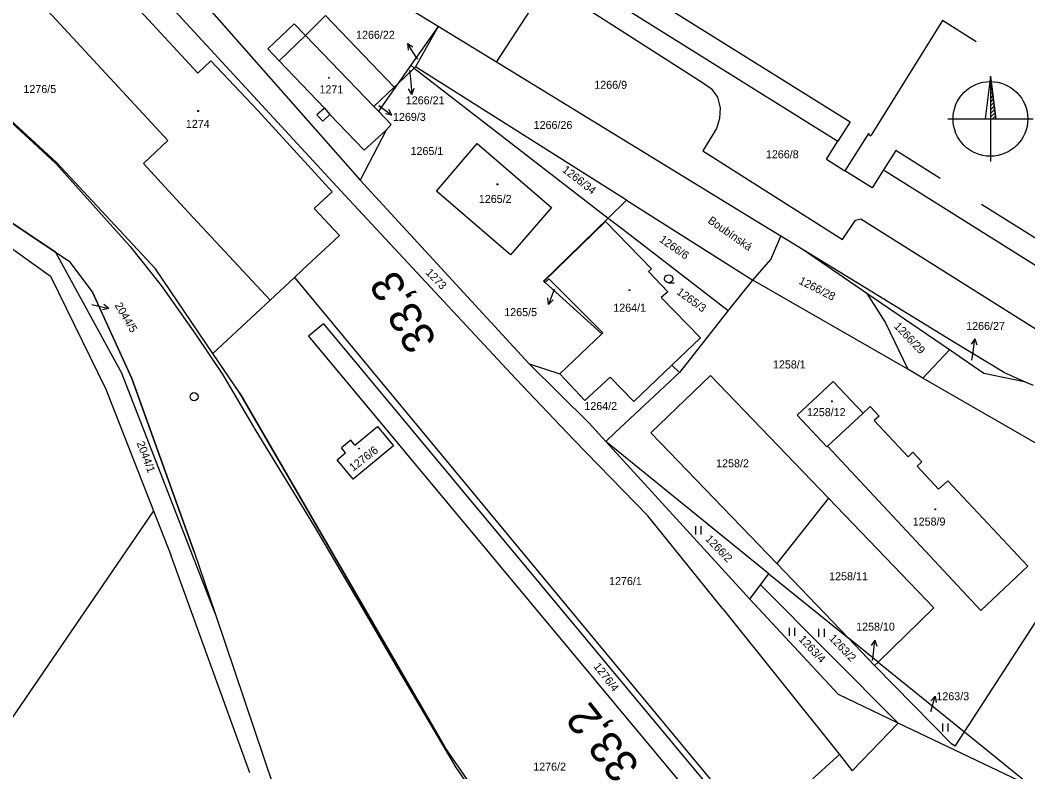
# Model space of a CAD drawing. Extents: x -805011 to -803920, y -1150790 to -1150234.
# Drawn here: x -804203.4 to -804014.7, y -1150647.5 to -1150506.7 of the extents above; entities that cross this region are included whole.
import ezdxf

# ---------------------------------------------------------------- set-up
doc = ezdxf.new("R2010")
doc.units = 0
for name, color, linetype in [('Default', 7, 'Continuous'), ('formát', 7, 'Continuous'), ('kilometráž - vrstava 7', 7, 'Continuous'), ('kn_celek - Cisla parcel pomocna', 7, 'Continuous'), ('kn_celek - Cisla pozemkovych parcel', 7, 'Continuous'), ('kn_celek - Cisla stavebnich parcel', 7, 'Continuous'), ('kn_celek - Dalsi prvky mapy popis', 7, 'Continuous'), ('kn_celek - Hranice parcel', 7, 'Continuous'), ('kn_celek - Vnitrni kresby', 7, 'Continuous'), ('kn_celek - Znacky budov', 7, 'Continuous'), ('kn_celek - Znacky kultur', 7, 'Continuous'), ('plochy - SZDC', 7, 'Continuous'), ('PSR_C2_2_trasa_Vimperk - Kabelová trasa', 7, 'Continuous')]:
    doc.layers.add(name, color=color, linetype=linetype)

# ---------------------------------------------------------------- blocks, each defined once
blk = doc.blocks.new('306')
at = {"layer": 'Default'}
for p, q in [((-5.2, 0), (-5.2, 15)), ((4.8, 0), (4.8, 15))]:
    blk.add_line(p, q, dxfattribs=at)
blk = doc.blocks.new('304')
at = {"layer": 'Default'}
blk.add_line((-0.1, 0), (9.9, 0), dxfattribs=at)
blk.add_circle((-0.1, 7.5), 7.5, dxfattribs=at)
blk = doc.blocks.new('402')
at = {"layer": 'Default'}
for p, q in [((-0.8, 0.8), (0.7, 0.8)), ((-0.8, 0.8), (-0.8, -0.7)), ((0.7, 0.8), (0.7, -0.7)), ((0.7, -0.7), (-0.8, -0.7))]:
    blk.add_line(p, q, dxfattribs=at)
blk = doc.blocks.new('Z61')
at = {"layer": 'Default'}
for p, q in [((0, 0), (30, 0)), ((30, 0), (19.2, 5.3)), ((30, 0), (19.2, -5.3))]:
    blk.add_line(p, q, dxfattribs=at)

msp = doc.modelspace()

# ---------------------------------------------------------------- linework, layer by layer
at = {"layer": 'formát'}
for p, q in [((-804021.69, -1150517.19), (-804021.69, -1150533.19)), ((-804021.69, -1150517.82), (-804021.62, -1150517.75)), ((-804021.69, -1150518.53), (-804021.54, -1150518.38)), ((-804021.69, -1150519.24), (-804021.46, -1150519.01)), ((-804021.69, -1150519.94), (-804021.38, -1150519.64)), ((-804021.69, -1150520.65), (-804021.31, -1150520.27)), ((-804021.69, -1150521.36), (-804021.23, -1150520.9)), ((-804021.69, -1150522.07), (-804021.15, -1150521.52)), ((-804021.69, -1150522.77), (-804021.07, -1150522.15)), ((-804021.69, -1150523.48), (-804020.99, -1150522.78)), ((-804021.69, -1150524.19), (-804020.91, -1150523.41)), ((-804029.69, -1150525.19), (-804013.69, -1150525.19)), ((-804021.69, -1150524.89), (-804020.83, -1150524.04)), ((-804021.28, -1150525.19), (-804020.76, -1150524.67))]:
    msp.add_line(p, q, dxfattribs=at)
for points in [[(-804021.69, -1150517.19), (-804022.69, -1150525.19)], [(-804021.69, -1150517.19), (-804020.69, -1150525.19)], [(-804021.69, -1150517.19), (-804021.69, -1150525.19), (-804020.69, -1150525.19), (-804021.69, -1150517.19)]]:
    msp.add_lwpolyline(points, dxfattribs=at)
msp.add_circle((-804021.69, -1150525.19), 7, dxfattribs=at)
at = {"layer": 'kilometráž - vrstava 7'}
msp.add_circle((-804170.87, -1150577.21), 0.75, dxfattribs=at)
at = {"layer": 'kn_celek - Cisla parcel pomocna'}
for p, q in [((-804128.97, -1150514.03), (-804129.25, -1150513.61)), ((-804130.49, -1150516.15), (-804130.35, -1150517.61)), ((-804190.03, -1150559.97), (-804189.75, -1150560.03)), ((-804025.16, -1150570.39), (-804025.01, -1150569.34)), ((-804043.76, -1150626.64), (-804043.67, -1150625.78))]:
    msp.add_line(p, q, dxfattribs=at)
at = {"layer": 'kn_celek - Hranice parcel'}
for p, q in [((-804111.38, -1150491.09), (-804050.27, -1150529.35)), ((-804192.55, -1150492.4), (-804170.14, -1150516.6)), ((-804099.45, -1150493.57), (-804047.98, -1150525.74)), ((-804206.45, -1150496.09), (-804175.77, -1150529.26)), ((-804181.12, -1150497.76), (-804142.6, -1150539.45)), ((-804169.49, -1150502.94), (-804139.75, -1150536.68)), ((-804100.25, -1150502.6), (-804075.6, -1150518.36)), ((-804125.16, -1150507.9), (-804129.95, -1150504.97)), ((-804114.2, -1150514.6), (-804106.86, -1150503.28)), ((-804150, -1150509.6), (-804146.22, -1150505.84)), ((-804133.38, -1150519.26), (-804146.22, -1150505.84)), ((-804030.68, -1150506.78), (-804044.05, -1150528.23)), ((-804030.68, -1150506.78), (-804030.58, -1150506.63)), ((-804024.36, -1150510.76), (-804030.68, -1150506.78)), ((-804152.14, -1150507.39), (-804157.04, -1150512.06)), ((-804152.14, -1150507.39), (-804150, -1150509.6)), ((-804125.16, -1150507.9), (-804130.26, -1150515.13)), ((-804125.16, -1150507.9), (-804129.38, -1150515.45)), ((-804114.2, -1150514.6), (-804125.16, -1150507.9)), ((-804157.04, -1150512.06), (-804154.91, -1150514.3)), ((-804170.14, -1150516.6), (-804167.75, -1150514.32)), ((-804167.75, -1150514.32), (-804158.94, -1150523.63)), ((-804154.91, -1150514.3), (-804146.45, -1150523.2)), ((-804216.71, -1150514.88), (-804196.65, -1150533.37)), ((-804130.26, -1150515.13), (-804132.75, -1150518.66)), ((-804129.63, -1150515.68), (-804132.75, -1150518.66)), ((-804129.63, -1150515.68), (-804130.26, -1150515.13)), ((-804129.63, -1150515.68), (-804129.38, -1150515.45)), ((-804129.63, -1150515.68), (-804093.31, -1150543.76)), ((-804089.88, -1150540.41), (-804129.38, -1150515.45)), ((-804066.19, -1150543.95), (-804114.2, -1150514.6)), ((-804075.6, -1150518.36), (-804074.02, -1150519.53)), ((-804137.16, -1150522.9), (-804133.38, -1150519.26)), ((-804132.75, -1150518.66), (-804136.34, -1150523.75)), ((-804133.38, -1150519.26), (-804132.75, -1150518.66)), ((-804074.02, -1150519.53), (-804072.81, -1150521.15)), ((-804072.81, -1150521.15), (-804072.3, -1150523.12)), ((-804158.94, -1150523.63), (-804149.5, -1150533.93)), ((-804146.45, -1150523.2), (-804147.85, -1150524.46)), ((-804137.16, -1150522.9), (-804136.34, -1150523.75)), ((-804136.34, -1150523.75), (-804133.93, -1150526.25)), ((-804072.3, -1150523.12), (-804072.44, -1150525.14)), ((-804147.85, -1150524.46), (-804146.75, -1150525.65)), ((-804146.75, -1150525.65), (-804145.46, -1150524.37)), ((-804145.46, -1150524.37), (-804138.99, -1150531.05)), ((-804072.44, -1150525.14), (-804073.01, -1150527.01)), ((-804047.98, -1150525.74), (-804050.27, -1150529.35)), ((-804134.88, -1150527.29), (-804139.75, -1150536.68)), ((-804134.88, -1150527.29), (-804138.99, -1150531.05)), ((-804133.93, -1150526.25), (-804134.88, -1150527.29)), ((-804073.01, -1150527.01), (-804075.59, -1150531.2)), ((-804180.36, -1150533.57), (-804175.77, -1150529.26)), ((-804052.42, -1150532.75), (-804050.27, -1150529.35)), ((-804044.52, -1150527.91), (-804048.97, -1150534.9)), ((-804044.52, -1150527.91), (-804044.39, -1150527.99)), ((-804044.39, -1150527.99), (-804044.48, -1150528.14)), ((-804044.48, -1150528.14), (-804044.14, -1150528.37)), ((-804044.14, -1150528.37), (-804044.05, -1150528.23)), ((-804125.44, -1150538.72), (-804117.85, -1150529.83)), ((-804117.85, -1150529.83), (-804103.93, -1150541.79)), ((-804075.59, -1150531.2), (-804049.42, -1150547.8)), ((-804039.43, -1150531.11), (-804041.71, -1150534.74)), ((-804031.12, -1150536.33), (-804039.43, -1150531.11)), ((-804178.11, -1150553.27), (-804196.65, -1150533.37)), ((-804052.42, -1150532.75), (-804048.97, -1150534.9)), ((-804175.65, -1150538.65), (-804180.36, -1150533.57)), ((-804149.5, -1150533.93), (-804144.98, -1150538.85)), ((-804043.84, -1150538.13), (-804048.97, -1150534.9)), ((-804041.71, -1150534.74), (-804043.84, -1150538.13)), ((-804041.71, -1150534.74), (-804011.88, -1150553.48)), ((-804139.75, -1150536.68), (-804108.11, -1150571.09)), ((-804171.88, -1150542.7), (-804175.65, -1150538.65)), ((-804144.98, -1150538.85), (-804147.36, -1150541.05)), ((-804111.56, -1150550.66), (-804125.44, -1150538.72)), ((-804110.61, -1150573.9), (-804142.6, -1150539.45)), ((-804089.88, -1150540.41), (-804093.31, -1150543.76)), ((-804089.88, -1150540.41), (-804066.17, -1150555.39)), ((-804156.63, -1150559.13), (-804171.88, -1150542.7)), ((-804147.36, -1150541.05), (-804148.35, -1150541.97)), ((-804148.35, -1150541.97), (-804143.64, -1150547.05)), ((-804103.93, -1150541.79), (-804111.56, -1150550.66)), ((-803998.28, -1150556.97), (-804023.33, -1150541.23)), ((-804196.79, -1150550.13), (-804207.3, -1150543.14)), ((-804105.39, -1150555.59), (-804093.31, -1150543.76)), ((-804105.33, -1150555.63), (-804093.82, -1150544.42)), ((-804093.82, -1150544.42), (-804085.19, -1150553.27)), ((-804093.31, -1150543.76), (-804090.57, -1150545.83)), ((-804060.93, -1150547.17), (-804066.19, -1150543.95)), ((-804049.42, -1150547.8), (-804046.98, -1150544.17)), ((-804046.98, -1150544.17), (-804045.99, -1150543.91)), ((-804045.99, -1150543.91), (-804012.15, -1150565.18)), ((-804210.52, -1150545.49), (-804197.78, -1150554.62)), ((-804090.57, -1150545.83), (-804070.79, -1150561.09)), ((-804143.64, -1150547.05), (-804150.56, -1150553.49)), ((-804062.82, -1150551.55), (-804060.93, -1150547.17)), ((-804056.75, -1150549.72), (-804060.93, -1150547.17)), ((-804196.79, -1150550.13), (-804184.3, -1150573.01)), ((-804196.79, -1150550.13), (-804194.25, -1150551.81)), ((-804045.51, -1150556.6), (-804056.75, -1150549.72)), ((-804044.84, -1150557.87), (-804056.75, -1150549.72)), ((-804194.25, -1150551.81), (-804189.84, -1150557.76)), ((-804066.17, -1150555.39), (-804062.82, -1150551.55)), ((-804167.37, -1150569.11), (-804178.11, -1150553.27)), ((-804150.56, -1150553.49), (-804152.05, -1150554.87)), ((-804085.19, -1150553.27), (-804085.71, -1150553.75)), ((-804085.71, -1150553.75), (-804082.14, -1150557.58)), ((-804197.78, -1150554.62), (-804187.36, -1150575.81)), ((-804152.05, -1150554.87), (-804156.63, -1150559.13)), ((-804152.05, -1150554.87), (-804065.98, -1150658.69)), ((-804105.33, -1150555.63), (-804105.39, -1150555.59)), ((-804105.33, -1150555.63), (-804105.37, -1150555.67)), ((-804105.37, -1150555.67), (-804105.13, -1150555.87)), ((-804105.13, -1150555.87), (-804105.1, -1150555.84)), ((-804105.1, -1150555.84), (-804104.39, -1150555.14)), ((-804105.1, -1150555.84), (-804094.46, -1150565.43)), ((-804094.27, -1150565.25), (-804104.39, -1150555.14)), ((-804070.57, -1150560.82), (-804066.17, -1150555.39)), ((-804037.19, -1150572.09), (-804066.17, -1150555.39)), ((-804182.55, -1150573.8), (-804189.84, -1150557.76)), ((-804082.14, -1150557.58), (-804083.36, -1150558.66)), ((-804028.2, -1150567.18), (-804045.51, -1150556.6)), ((-804044.84, -1150557.87), (-804041.37, -1150563.36)), ((-804029.38, -1150568.44), (-804044.84, -1150557.87)), ((-804167.37, -1150569.11), (-804156.63, -1150559.13)), ((-804083.36, -1150558.66), (-804076.02, -1150566.18)), ((-804070.79, -1150561.09), (-804079.95, -1150572.68)), ((-804070.57, -1150560.82), (-804070.79, -1150561.09)), ((-804146.64, -1150563.54), (-804149.4, -1150565.85)), ((-804146.64, -1150563.54), (-804062.82, -1150664.2)), ((-804041.37, -1150563.36), (-804037.19, -1150572.09)), ((-804102.34, -1150572.92), (-804094.46, -1150565.43)), ((-804094.46, -1150565.43), (-804094.27, -1150565.25)), ((-804149.4, -1150565.85), (-804065.57, -1150666.5)), ((-804081.39, -1150571.32), (-804076.02, -1150566.18)), ((-804019.25, -1150572.65), (-804028.2, -1150567.18)), ((-804162.29, -1150576.56), (-804167.37, -1150569.11)), ((-804029.38, -1150568.44), (-804034.33, -1150573.74)), ((-804022.9, -1150572.87), (-804029.38, -1150568.44)), ((-804108.11, -1150571.09), (-804096.87, -1150582.16)), ((-804108.11, -1150571.09), (-804102.34, -1150572.92)), ((-804166.92, -1150617.84), (-804184.3, -1150573.01)), ((-804102.34, -1150572.92), (-804097.69, -1150577.93)), ((-804079.95, -1150572.68), (-804091.98, -1150583.92)), ((-804081.39, -1150571.32), (-804088.5, -1150578.14)), ((-804079.95, -1150572.68), (-804081.39, -1150571.32)), ((-804034.33, -1150573.74), (-804037.19, -1150572.09)), ((-804015.03, -1150574.48), (-804022.9, -1150572.87)), ((-804019.25, -1150572.65), (-804015.03, -1150574.48)), ((-804170.78, -1150606.46), (-804182.55, -1150573.8)), ((-804099.79, -1150585.26), (-804110.61, -1150573.9)), ((-804092.89, -1150573.55), (-804097.69, -1150577.93)), ((-804088.5, -1150578.14), (-804092.89, -1150573.55)), ((-804085.27, -1150584), (-804074.15, -1150573.25)), ((-804074.15, -1150573.25), (-804052.05, -1150596.22)), ((-804057.86, -1150580.66), (-804051.13, -1150574.38)), ((-804051.13, -1150574.38), (-804045.54, -1150580.31)), ((-804009.91, -1150587.8), (-804034.33, -1150573.74)), ((-804015.03, -1150574.48), (-804013.7, -1150575.06)), ((-804187.36, -1150575.81), (-804178.44, -1150598.56)), ((-804162.29, -1150576.56), (-804123.96, -1150642.72)), ((-804052.2, -1150586.48), (-804045.54, -1150580.31)), ((-804045.54, -1150580.31), (-804044.21, -1150579.08)), ((-804044.21, -1150579.08), (-804042.55, -1150580.86)), ((-804096.87, -1150582.16), (-804093.7, -1150585.63)), ((-804052.31, -1150586.58), (-804057.86, -1150580.66)), ((-804042.55, -1150580.86), (-804043.44, -1150581.68)), ((-804043.44, -1150581.68), (-804037.1, -1150588.46)), ((-804140.72, -1150586.29), (-804136.48, -1150582.8)), ((-804136.48, -1150582.8), (-804133.52, -1150586.39)), ((-804093.7, -1150585.63), (-804091.98, -1150583.92)), ((-804061.72, -1150608.48), (-804085.27, -1150584)), ((-804141.49, -1150585.36), (-804143.27, -1150586.79)), ((-804140.72, -1150586.29), (-804141.49, -1150585.36)), ((-804085.89, -1150599.5), (-804099.79, -1150585.26)), ((-804093.7, -1150585.63), (-804066.74, -1150615.12)), ((-804063.22, -1150610.38), (-804093.7, -1150585.63)), ((-804144.04, -1150589.01), (-804142.48, -1150587.74)), ((-804142.48, -1150587.74), (-804143.27, -1150586.79)), ((-804133.52, -1150586.39), (-804141.08, -1150592.64)), ((-804052.2, -1150586.48), (-804052.31, -1150586.58)), ((-804023.47, -1150617.24), (-804052.2, -1150586.48)), ((-804037.1, -1150588.46), (-804036.2, -1150587.63)), ((-804036.2, -1150587.63), (-804034.55, -1150589.42)), ((-804141.08, -1150592.64), (-804144.04, -1150589.01)), ((-804034.55, -1150589.42), (-804035.44, -1150590.24)), ((-804035.44, -1150590.24), (-804031.43, -1150594.53)), ((-804031.43, -1150594.53), (-804029.68, -1150592.95)), ((-804029.68, -1150592.95), (-804014.66, -1150608.98)), ((-804052.05, -1150596.22), (-804061.72, -1150608.48)), ((-804052.05, -1150596.22), (-804032.3, -1150616.75)), ((-804178.44, -1150598.56), (-804205.91, -1150638.78)), ((-804178.44, -1150598.56), (-804175.13, -1150607.01)), ((-804071.82, -1150616.91), (-804085.89, -1150599.5)), ((-804160.41, -1150647.65), (-804175.13, -1150607.01)), ((-804170.78, -1150606.46), (-804166.92, -1150617.84)), ((-804048.33, -1150622.39), (-804061.72, -1150608.48)), ((-804064.75, -1150612.44), (-804063.22, -1150610.38)), ((-804063.22, -1150610.38), (-804048.33, -1150622.39)), ((-804014.66, -1150608.98), (-804023.47, -1150617.24)), ((-804066.74, -1150615.12), (-804064.75, -1150612.44)), ((-804064.75, -1150612.44), (-804038.96, -1150638.33)), ((-804050.17, -1150633), (-804066.74, -1150615.12)), ((-804166.92, -1150617.84), (-804155.97, -1150650.2)), ((-804071.82, -1150616.91), (-804049.99, -1150644.23)), ((-804032.3, -1150616.75), (-804042.74, -1150626.9)), ((-804025.71, -1150638.73), (-804012.48, -1150618.32)), ((-804043.39, -1150627.53), (-804048.33, -1150622.39)), ((-804042.74, -1150626.9), (-804048.33, -1150622.39)), ((-804042.74, -1150626.9), (-804043.39, -1150627.53)), ((-804028.9, -1150642.28), (-804043.39, -1150627.53)), ((-804042.74, -1150626.9), (-804026.54, -1150639.97)), ((-804038.96, -1150638.33), (-804050.17, -1150633)), ((-804047.57, -1150647.28), (-804038.96, -1150638.33)), ((-804028.35, -1150643.39), (-804038.96, -1150638.33)), ((-804026.54, -1150639.97), (-804025.71, -1150638.73)), ((-804028.32, -1150642.67), (-804026.54, -1150639.97)), ((-804026.54, -1150639.97), (-804013.68, -1150650.38)), ((-804111.51, -1150660.72), (-804123.96, -1150642.72)), ((-804028.32, -1150642.67), (-804028.9, -1150642.28)), ((-804051.16, -1150645.3), (-804049.99, -1150644.23)), ((-804049.99, -1150644.23), (-804047.57, -1150647.28)), ((-804013.68, -1150650.38), (-804028.35, -1150643.39)), ((-804065.98, -1150658.69), (-804051.16, -1150645.3))]:
    msp.add_line(p, q, dxfattribs=at)
at = {"layer": 'kn_celek - Vnitrni kresby'}
for p, q in [((-804150, -1150509.6), (-804154.91, -1150514.3)), ((-804150, -1150509.6), (-804137.16, -1150522.9)), ((-804146.45, -1150523.2), (-804145.46, -1150524.37))]:
    msp.add_line(p, q, dxfattribs=at)
at = {"layer": 'plochy - SZDC'}
for p, q in [((-804196.65, -1150533.37), (-804216.71, -1150514.88)), ((-804178.11, -1150553.27), (-804196.65, -1150533.37)), ((-804207.3, -1150543.14), (-804196.79, -1150550.13)), ((-804196.79, -1150550.13), (-804194.25, -1150551.81)), ((-804194.25, -1150551.81), (-804189.84, -1150557.76)), ((-804167.37, -1150569.11), (-804178.11, -1150553.27)), ((-804162.29, -1150576.56), (-804167.37, -1150569.11)), ((-804182.55, -1150573.8), (-804170.78, -1150606.46)), ((-804123.96, -1150642.72), (-804162.29, -1150576.56)), ((-804170.78, -1150606.46), (-804166.92, -1150617.84)), ((-804166.92, -1150617.84), (-804155.97, -1150650.2)), ((-804111.51, -1150660.72), (-804123.96, -1150642.72))]:
    msp.add_line(p, q, dxfattribs=at)
msp.add_lwpolyline([(-804189.84, -1150557.76), (-804188.7, -1150560.27), (-804182.55, -1150573.8)], dxfattribs=at)
at = {"layer": 'PSR_C2_2_trasa_Vimperk - Kabelová trasa'}
msp.add_lwpolyline([(-804211.94, -1150528.21), (-804207.53, -1150523.61), (-804196.77, -1150533.52), (-804182.83, -1150549.06), (-804177, -1150556.4), (-804170.6, -1150565.5), (-804165.46, -1150573.1), (-804159.32, -1150583.6), (-804148.34, -1150601.45), (-804139.82, -1150616.03), (-804133.21, -1150627.36), (-804121.85, -1150646.68), (-804112.03, -1150660.85), (-804099.51, -1150673.08)], dxfattribs=at)

# ---------------------------------------------------------------- block references
at = {"layer": 'kn_celek - Cisla parcel pomocna'}
for p, xscale, yscale, rotation in [((-804129.25, -1150513.61), 0.09999999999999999, 0.10000000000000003, 123.23628000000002), ((-804130.35, -1150517.61), 0.1, 0.10000000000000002, -84.48056999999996), ((-804136.24, -1150522.68), 0.1, 0.10000000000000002, -36.86994000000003), ((-804103.43, -1150557.12), 0.1, 0.10000000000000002, -110.55600000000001), ((-804189.75, -1150560.03), 0.10000000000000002, 0.09999999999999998, -12.850650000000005), ((-804025.01, -1150569.34), 0.1, 0.09999999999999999, 81.9297), ((-804043.67, -1150625.78), 0.1, 0.10000000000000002, 84.05316000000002), ((-804032.88, -1150636.15), 0.09999999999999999, 0.09999999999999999, 73.30086000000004)]:
    msp.add_blockref('Z61', p, dxfattribs=dict(at, xscale=xscale, yscale=yscale, rotation=rotation))
at = {"layer": 'kn_celek - Znacky budov', "xscale": 0.1, "yscale": 0.10000000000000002}
for p in [(-804145.63, -1150517.51), (-804170.13, -1150523.71), (-804114.05, -1150537.46), (-804089.33, -1150557.27), (-804051.39, -1150578.08), (-804140.01, -1150586.92), (-804032.02, -1150598.31)]:
    msp.add_blockref('402', p, dxfattribs=at)
at = {"layer": 'kn_celek - Znacky kultur', "xscale": 0.1, "yscale": 0.10000000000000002}
for name, p in [('304', (-804081.95, -1150555.89)), ('306', (-804076.37, -1150602.99)), ('306', (-804058.82, -1150621.97)), ('306', (-804053.28, -1150622.16)), ('306', (-804030.09, -1150639.93))]:
    msp.add_blockref(name, p, dxfattribs=at)

# ---------------------------------------------------------------- texts
at = {"layer": 'kilometráž - vrstava 7'}
for s, rotation, p in [('33,3', 119.9223, (-804125.27, -1150566.7)), ('33,2', 128.139, (-804087.18, -1150646.31))]:
    msp.add_text(s, height=6, rotation=rotation, dxfattribs=at).set_placement(p)
at = {"layer": 'kn_celek - Cisla parcel pomocna'}
for s, p in [('1266/22', (-804140.52, -1150510.2)), ('1266/21', (-804131.2, -1150522.47)), ('1269/3', (-804133.6, -1150525.57)), ('1265/5', (-804112.75, -1150562.13)), ('1266/27', (-804026.23, -1150564.72)), ('1258/10', (-804046.84, -1150621.03)), ('1263/3', (-804031.81, -1150634.06))]:
    msp.add_text(s, height=1.5, dxfattribs=at).set_placement(p)
msp.add_text('2044/5', height=1.5, rotation=300.8069, dxfattribs=at).set_placement((-804185.79, -1150560.1))
at = {"layer": 'kn_celek - Cisla pozemkovych parcel'}
for s, height, p in [('1266/22', 0.1, (-804129.28, -1150514)), ('1266/21', 0.1, (-804130.78, -1150516.12)), ('1266/9', 1.5, (-804095.89, -1150519.56)), ('1276/5', 1.5, (-804202.83, -1150520.35)), ('1269/3', 0.1, (-804136.24, -1150522.65)), ('1266/26', 1.5, (-804107.25, -1150527.08)), ('1265/1', 1.5, (-804130.31, -1150531.96)), ('1266/8', 1.5, (-804063.74, -1150532.57)), ('1265/5', 0.1, (-804103.43, -1150557.09)), ('1258/1', 1.5, (-804062.42, -1150571.93)), ('1266/27', 0.1, (-804025.47, -1150570.36)), ('1264/2', 1.5, (-804097.75, -1150579.71)), ('1258/2', 1.5, (-804073.07, -1150590.44)), ('1258/11', 1.5, (-804051.9, -1150611.59)), ('1276/1', 1.5, (-804093.13, -1150612.49)), ('1258/10', 0.1, (-804044.06, -1150626.61)), ('1263/3', 0.1, (-804032.88, -1150636.12)), ('1276/2', 1.5, (-804107.33, -1150647.25))]:
    msp.add_text(s, height=height, dxfattribs=at).set_placement(p)
for s, height, rotation, p in [('1266/34', 1.5, 322.0308, (-804102.02, -1150534.97)), ('1266/6', 1.5, 324.9, (-804083.84, -1150548.08)), ('1273', 1.5, 314.1, (-804127.59, -1150554.08)), ('1266/28', 1.5, 333.1986, (-804057.71, -1150555.99)), ('1265/3', 1.5, 324, (-804080.59, -1150557.88)), ('2044/5', 0.1, 297, (-804190.2, -1150559.75)), ('1266/29', 1.5, 313.7083, (-804039.85, -1150564.13)), ('2044/1', 1.5, 290.7, (-804181.64, -1150585.88)), ('1266/2', 1.5, 314.1, (-804075.21, -1150603.96)), ('1263/4', 1.5, 313.2673, (-804057.7, -1150622.73)), ('1263/2', 1.5, 313.6896, (-804052.02, -1150622.54)), ('1276/4', 1.5, 307.8, (-804096.11, -1150627.75))]:
    msp.add_text(s, height=height, rotation=rotation, dxfattribs=at).set_placement(p)
at = {"layer": 'kn_celek - Cisla stavebnich parcel'}
for s, p in [('1271', (-804147.37, -1150520.42)), ('1274', (-804172.4, -1150526.88)), ('1265/2', (-804117.52, -1150540.93)), ('1264/1', (-804092.33, -1150561.3)), ('1258/12', (-804056.07, -1150580.86)), ('1258/9', (-804036.25, -1150601.35))]:
    msp.add_text(s, height=1.5, dxfattribs=at).set_placement(p)
msp.add_text('1276/6', height=1.5, rotation=37.8, dxfattribs=at).set_placement((-804141.07, -1150591.27))
at = {"layer": 'kn_celek - Dalsi prvky mapy popis'}
msp.add_text('Boubínská', height=1.5, rotation=325.0319, dxfattribs=at).set_placement((-804074.75, -1150544.54))

doc.saveas('drawing.dxf')
